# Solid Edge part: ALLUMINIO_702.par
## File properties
Subject: ALLUMINIO_702
Author: f_grande
Template: Normal.par
Last saved by: f_grande
Revision: 11
Application: Solid Edge
Densità: 2712,000 kg/m^3
Precisione: 0,990
Tipo di contenuto documento: 0
Document Number: KR0101
Material: Alluminio, 1060
Stile della faccia: Alluminio
Stile di riempimento: ANSI38(Alluminio)
Stile virtuale: Alluminio lucidato
Coef. of Thermal Exp: 0.0
Thermal Conductivity: 221.0
Specific Heat: 920.0
Modulus of Elasticity: 68947570000.0
Poisson's Ratio: 0.33
Yield Stress: 27579028.0
Ultimate Stress: 68947570.0
Elongation: 0.0
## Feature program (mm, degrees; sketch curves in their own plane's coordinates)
sketch for "unnamed Protrusion 1" #1 plane through (0, 0, 0) normal (0, -1, 0) x-axis (1, 0, 0)
  line (2.4, -2.4) -> (13.3, -2.4)
  line (13.3, -2.4) -> (13.3, -13.3)
  line (13.3, -13.3) -> (2.4, -13.3)
  line (2.4, -13.3) -> (2.4, -2.4)
sketch for "unnamed Protrusion 1" #2 plane through (0, 0, 0) normal (0, -1, 0) x-axis (1, 0, 0)
  line (18.3, 0) -> (18.3, -4.5)
  line (18.3, -4.5) -> (15.7, -4.5)
  line (15.7, -4.5) -> (15.7, -12.8)
  arc centre (18.7, -12.8) radius 3 from (18.7, -15.8) to (15.7, -12.8) cw
  line (18.7, -15.8) -> (22.5, -15.8)
  line (22.5, -15.8) -> (22.5, -19.05)
  line (22.5, -26.05) -> (22.5, -33.2)
  line (14.5, -33.2) -> (22.5, -33.2)
  line (14.5, -34.2) -> (14.5, -33.2)
  line (2.4, -34.2) -> (14.5, -34.2)
  line (2.4, -47.5) -> (2.4, -34.2)
  line (0, -47.5) -> (2.4, -47.5)
  line (0, -26.8) -> (0, -47.5)
  line (0, -26.8) -> (4.7588, -26.8)
  line (4.7588, -26.8) -> (4.7588, -29.0094)
  line (4.7588, -29.0094) -> (12.8, -29.0094)
  arc centre (12.8, -26.0094) radius 3 from (12.8, -29.0094) to (15.8, -26.0094) ccw
  line (15.8, -18.7) -> (15.8, -26.0094)
  arc centre (12.8, -18.7) radius 3 from (12.8, -15.7) to (15.8, -18.7) cw
  line (4.5, -15.7) -> (12.8, -15.7)
  line (4.5, -18.3) -> (4.5, -15.7)
  line (0, -18.3) -> (4.5, -18.3)
  line (0, -2.4) -> (0, -18.3)
  arc centre (2.4, -2.4) radius 2.4 from (2.4, 0) to (0, -2.4) ccw
  line (2.4, 0) -> (18.3, 0)
  dimension (linear) = 18.3
  dimension (linear) = 18.3
  dimension (linear) = 4.5
  dimension (linear) = 18.7
  dimension (linear) = 2.4
  dimension (linear) = 15.7
  dimension (linear) = 4.7588
  dimension (linear) = 4.7588
  dimension (linear) = 15.8
  dimension (linear) = 2.4
  dimension (linear) = 2.4
  dimension (linear) = 2.4
  dimension (linear) = 2.4
  dimension (linear) = 14.5
  dimension (linear) = 14.5
  dimension (linear) = 22.5
  dimension (linear) = 22.5
extrude "unnamed Protrusion 1" add finite 702 along -normal
body pattern "unnamed BodyPattern 1"
pattern "unnamed Pattern 1"
body pattern "unnamed BodyPattern 2"
pattern "unnamed Pattern 2"
thread "unnamed Thread 1"
thread "unnamed Thread 2"
sketch for "ExtrudedCutout_1" #1 plane through (0, 351, -47.5) normal (-1, 0, 0) x-axis (0, 1, 0)
sketch for "ExtrudedCutout_1" #2 plane through (0, 351, -47.5) normal (-1, 0, 0) x-axis (0, 1, 0)
  circle centre (-278.2, 2.4) radius 3.5
sketch for "ExtrudedCutout_1" #3 plane through (0, 351, -47.5) normal (-1, 0, 0) x-axis (0, 1, 0)
  circle centre (278.2, 2.4) radius 3.5
sketch for "ExtrudedCutout_1" #4 plane through (0, 351, -47.5) normal (-1, 0, 0) x-axis (0, 1, 0)
extrude "ExtrudedCutout_1" cut finite 261.8883 along -normal
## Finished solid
Body 1: solid body, 108 faces, 308 edges, 192 vertices.
  Faces by surface: plane 82, cylinder 26
  Edges by curve: line 256, circle 52
Bounding box of the edges (mm): 45.000 x 702.000 x 95.000, from (0, 0, -95) to (45, 702, 0).
Cylindrical faces by radius (mm): R2.4 x4, R3 x12, R3.5 x10
Planar faces by outward normal: +x 20, +y 1, +z 20, -x 20, -y 1, -z 20
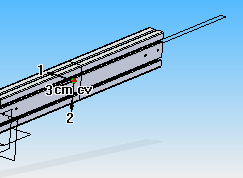
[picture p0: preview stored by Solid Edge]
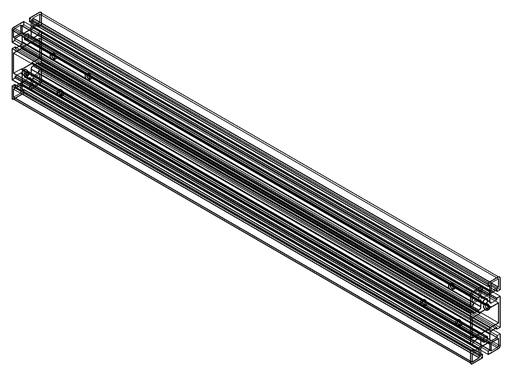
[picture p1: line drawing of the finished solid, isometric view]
